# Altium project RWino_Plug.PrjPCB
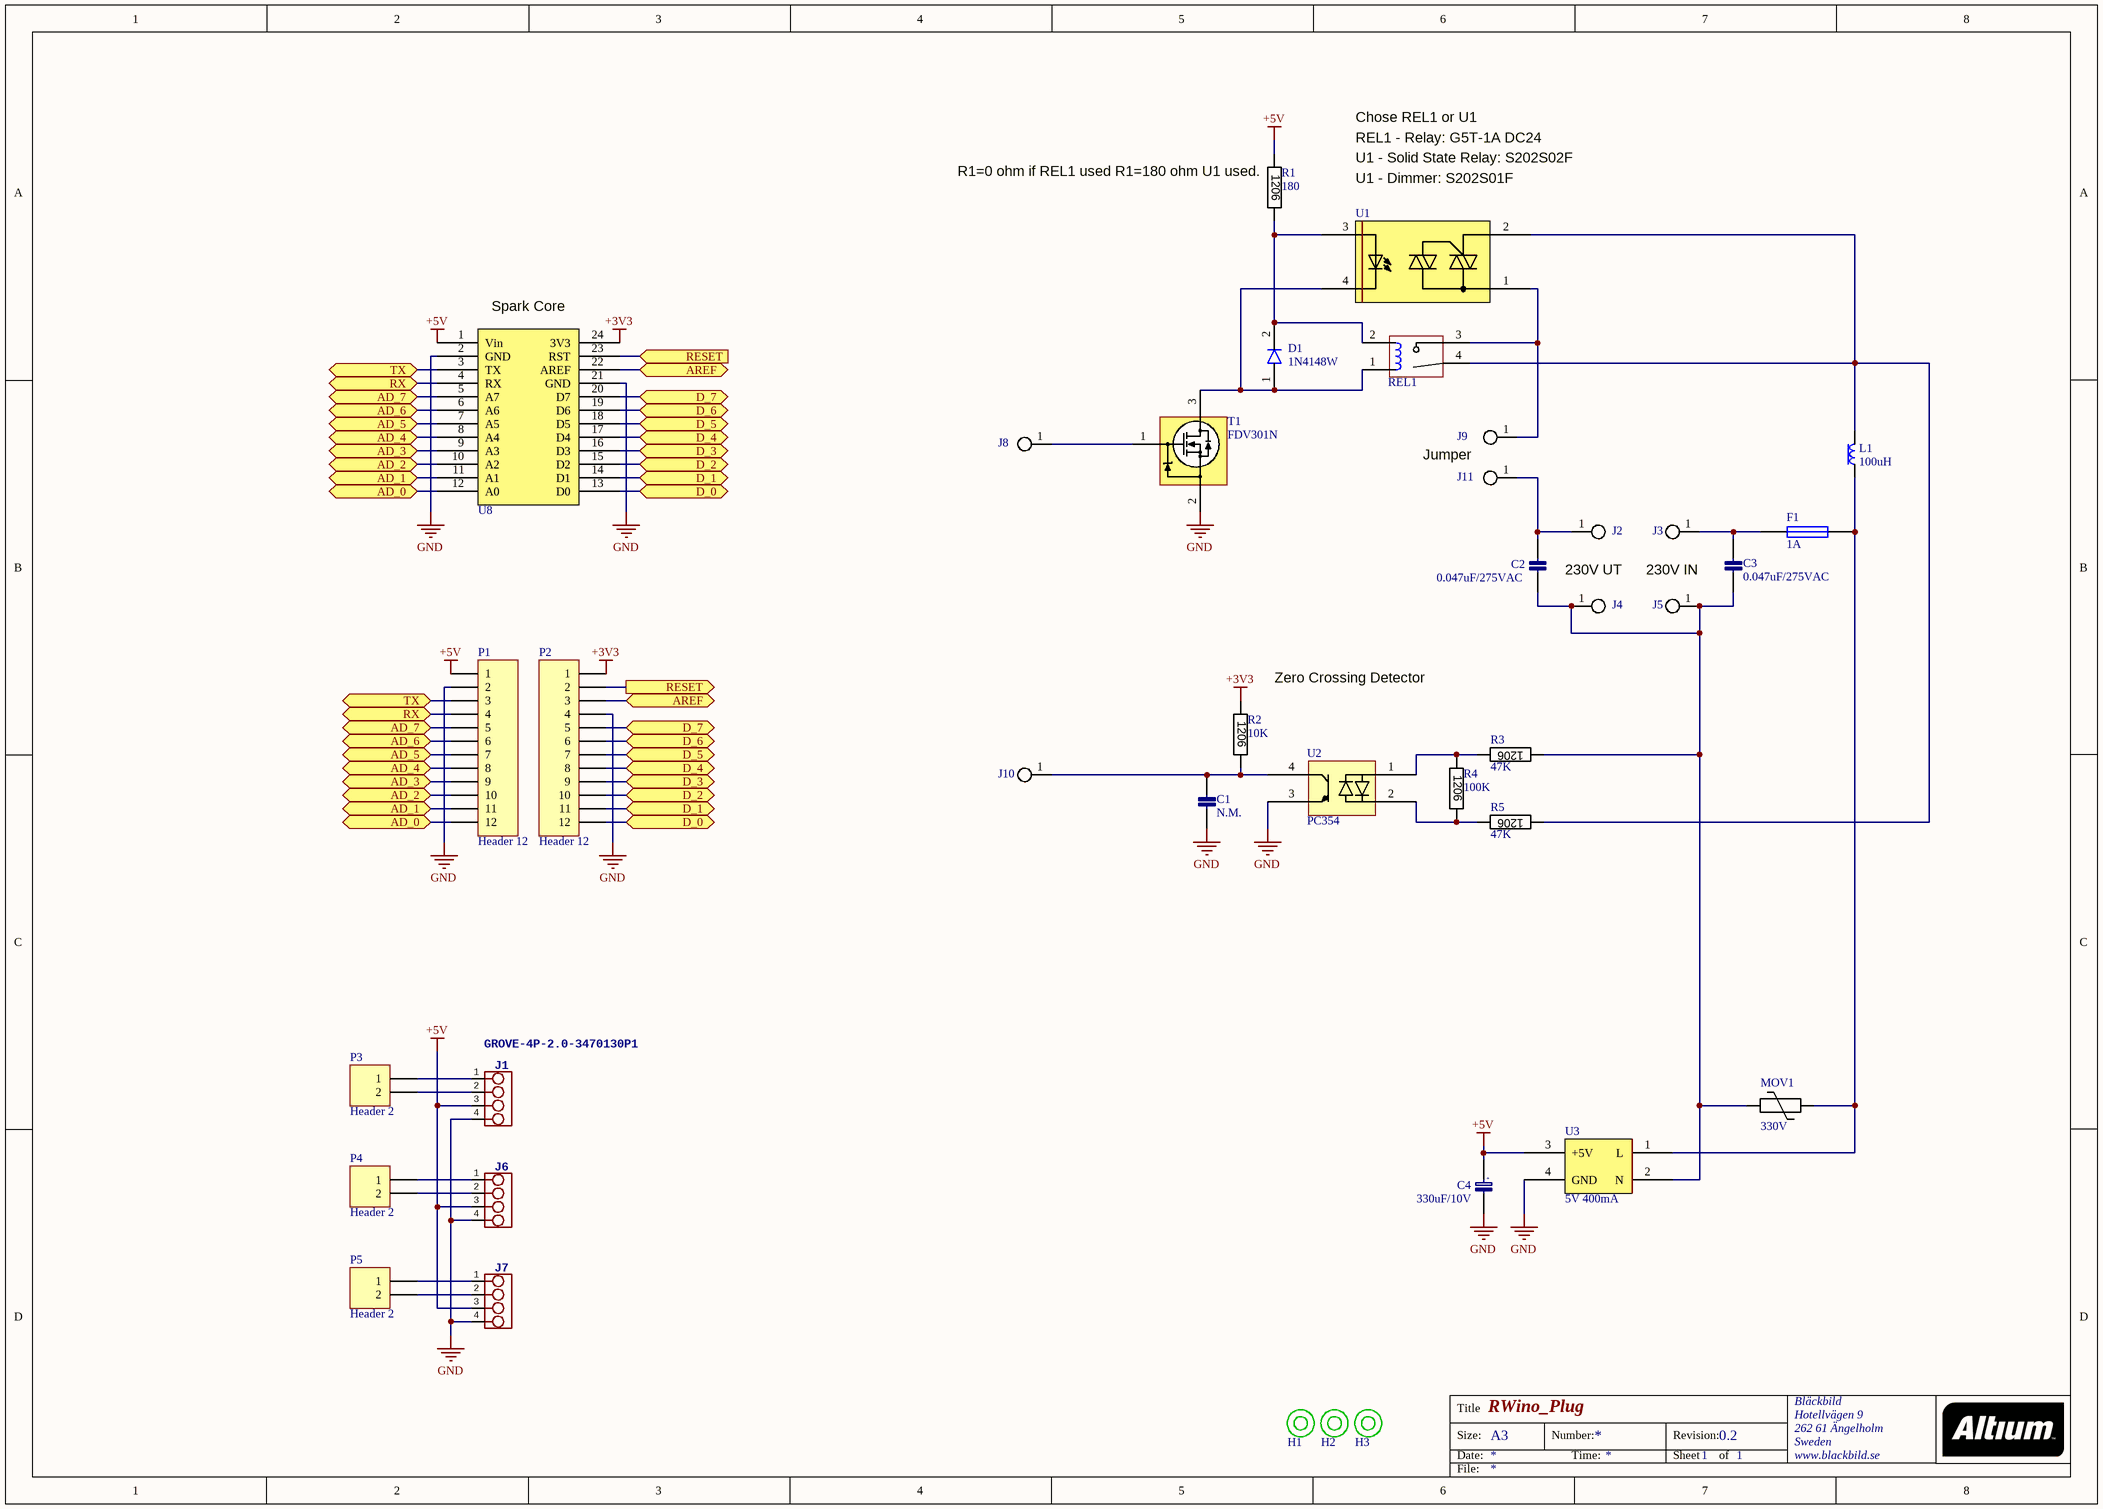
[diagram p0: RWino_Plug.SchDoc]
1 sheet, 38 parts. Net scope: flat (ports and power ports of the same name join across sheets).
Board file: RWino_Plug.PcbDoc

## Sheet RWino_Plug.SchDoc: RWino_Plug
size A3; Organization: Bläckbild; Address1: Hotellvägen 9; Address2: 262 61 Ängelholm; Address3: Sweden; Address4: www.blackbild.se; Revision: 0.2; SheetNumber: 1; SheetTotal: 1

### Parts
C1  value N.M.  [CAPC1206(3216)75_N]  (hidden comment: Ccap)
C2  value 0.047uF/275VAC  [PolyCap_0,047uF/275V]  (hidden comment: 0,047uF/275VAC)
C3  value 0.047uF/275VAC  [PolyCap_0,047uF/275V]  (hidden comment: 0,047uF/275VAC)
C4  value 330uF/10V  [T_Cap_D/7343-31]  (hidden comment: 330uF_Tcap)
D1  1N4148W  [SOD123F]
F1  value 1A  [PIN-W2/E2.8]  (hidden comment: Fuse 1)
H1  Fidus  [Fidus]  (value not drawn)
H2  Fidus  [Fidus]  (value not drawn)
H3  Fidus  [Fidus]  (value not drawn)
J1  GROVE-4P-2.0-3470130P1  [4P-2.0]
J2  Proto_PAD 1.87 mm  [Proto_PAD 1.87 mm]  (value not drawn)
J3  Proto_PAD 1.87 mm  [Proto_PAD 1.87 mm]  (value not drawn)
J4  Proto_PAD 1.87 mm  [Proto_PAD 1.87 mm]  (value not drawn)
J5  Proto_PAD 1.87 mm  [Proto_PAD 1.87 mm]  (value not drawn)
J6  GROVE-4P-2.0-3470130P1  [4P-2.0]  (value not drawn)
J7  GROVE-4P-2.0-3470130P1  [4P-2.0]  (value not drawn)
J8  Proto_PAD 1.87 mm  [Proto_PAD 1.87 mm]  (value not drawn)
J9  Proto_PAD 1.87 mm  [Proto_PAD 1.87 mm]  (value not drawn)
J10  Proto_PAD 1.87 mm  [Proto_PAD 1.87 mm]  (value not drawn)
J11  Proto_PAD 1.87 mm  [Proto_PAD 1.87 mm]  (value not drawn)
L1  100uH  [INDUCTOR 100UH/3A]
MOV1  value 330V  [MOV-14D]  (hidden comment: MOV-14D)
P1  Header 12  [HDR1X12]
P2  Header 12  [HDR1X12]
P3  Header 2  [HDR1X2]
P4  Header 2  [HDR1X2]
P5  Header 2  [HDR1X2]
R1  value 180  [RES1206_33mW]  (hidden comment: R1206)
R2  value 10K  [RES1206_33mW]  (hidden comment: R1206)
R3  value 47K  [RES1206_33mW]  (hidden comment: R1206)
R4  value 100K  [RES1206_33mW]  (hidden comment: R1206)
R5  value 47K  [RES1206_33mW]  (hidden comment: R1206)
REL1  G5T-1A DC24  [G5T-1A]  (value not drawn)
T1  FDV301N  [SOT23]
U1  S202S01F  [S202S01 Series]  (value not drawn)
U2  PC354  [4-SMD]
U3  value 5V 400mA  [RAC02-05SC]  (hidden comment: RAC02-05SC)
U8  Spark Core  [Spark_Core]  (value not drawn)

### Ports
AD_0 (bidir), AD_1 (bidir), AD_2 (bidir), AD_3 (bidir), AD_4 (bidir), AD_5 (bidir), AD_6 (bidir), AD_7 (bidir), AREF (bidir), D_0 (bidir), D_1 (bidir), D_2 (bidir), D_3 (bidir), D_4 (bidir), D_5 (bidir), D_6 (bidir), D_7 (bidir), RESET (in), RESET (out), RX (bidir), TX (bidir)

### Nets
+3V3: P2.1 R2.2 U8.24(3V3)
+5V: C4.1 J1.3 J6.3 J7.3 P1.1 R1.2 U3.3(+5V) U8.1(Vin)
GND: C1.2 C4.2 J1.4 J6.4 J7.4 P1.2 P2.4 T1.2(S) U2.3(E) U3.4(GND) U8.2(GND) U8.21(GND)
NetC1_1: C1.1 J10.1 R2.1 U2.4(C)
NetC2_1: C2.1 J2.1 J11.1
NetC2_2: C2.2 C3.2 J4.1 J5.1 MOV1.2 R3.2 U3.2(N)
NetC3_1: C3.1 F1.2 J3.1
NetD1_1: D1.1(A) REL1.1 T1.3 U1.4
NetD1_2: D1.2(C) R1.1 REL1.2 U1.3
NetF1_1: F1.1 L1.1 MOV1.1 U3.1(L)
NetJ1_1: J1.1 P3.1
NetJ1_2: J1.2 P3.2
NetJ6_1: J6.1 P4.1
NetJ6_2: J6.2 P4.2
NetJ7_1: J7.1 P5.1
NetJ7_2: J7.2 P5.2
NetJ8_1: J8.1 T1.1(G)
NetJ9_1: J9.1 REL1.3 U1.1
NetL1_2: L1.2 R5.2 REL1.4 U1.2
NetP1_3: P1.3 U8.3(TX) ; port TX
NetP1_4: P1.4 U8.4(RX) ; port RX
NetP1_5: P1.5 U8.5(A7) ; port AD_7
NetP1_6: P1.6 U8.6(A6) ; port AD_6
NetP1_7: P1.7 U8.7(A5) ; port AD_5
NetP1_8: P1.8 U8.8(A4) ; port AD_4
NetP1_9: P1.9 U8.9(A3) ; port AD_3
NetP1_10: P1.10 U8.10(A2) ; port AD_2
NetP1_11: P1.11 U8.11(A1) ; port AD_1
NetP1_12: P1.12 U8.12(A0) ; port AD_0
NetP2_2: P2.2 U8.23(RST) ; port RESET
NetP2_3: P2.3 U8.22(AREF) ; port AREF
NetP2_5: P2.5 U8.20(D7) ; port D_7
NetP2_6: P2.6 U8.19(D6) ; port D_6
NetP2_7: P2.7 U8.18(D5) ; port D_5
NetP2_8: P2.8 U8.17(D4) ; port D_4
NetP2_9: P2.9 U8.16(D3) ; port D_3
NetP2_10: P2.10 U8.15(D2) ; port D_2
NetP2_11: P2.11 U8.14(D1) ; port D_1
NetP2_12: P2.12 U8.13(D0) ; port D_0
NetR3_1: R3.1 R4.2 U2.1(A)
NetR4_1: R4.1 R5.1 U2.2(C)

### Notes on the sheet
- (near R1) R1=0 ohm if REL1 used R1=180 ohm U1 used.
- REL1 - Relay: G5T-1A DC24
- U1 - Solid State Relay: S202S02F
- (near U1) U1 - Dimmer: S202S01F
- Chose REL1 or U1
- (near U8) Spark Core
- Jumper
- 230V UT
- 230V IN
- (near R2) Zero Crossing Detector

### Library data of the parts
C1 = Ccap: Multilayer Ceramic Chip Capacitors X7R
C2 C3 = PolyCap_0.047uF/275VAC: Metallized Polypropylene Film EMI Suppression Capacitors 275VAC; Manufactor: Kemet; Manufactor ID: R46KF247050N0K; Suplayer ID: 399-11478-ND
C4 = 330uF_Tcap: Aluminum Electrolytic Type / Surface Mount Type; Manufactor: KEMET; Manufactor ID: T495X337K010ATE035; Suplayer ID: 399-4783-1-ND
D1 = 1N4148W: BAV16W/1N4148W - SURFACE MOUNT FAST SWITCHING DIODE; Manufactor: Fairchild; Manufactor ID: 1N4148WS; Suplayer ID: 1N4148WSFSCT-ND
F1 = Fuse 1: Fuse
J2-J5 J8-J11 = Proto_PAD 1.87 mm: Prototyp Pad 1.87 mm
L1 = Iductor 100uH/3A: Choke Power Inductor  100uH 3A; Manufactor: Talema Group LLC; Manufactor ID: DPO-3.0-100; Suplayer ID: 1295-1171-ND
MOV1 = MOV-14D: MOV-14DxxxK Series - Metal Oxide Varistor; Manufactor: Bourns; Manufactor ID: MOV-14D361K; Suplayer ID: MOV-14D361K-ND
P1 P2 = Header 12: Header, 12-Pin
P3-P5 = Header 2: Header, 2-Pin
R1 = R1206: Anti-Surge Thick Film Chip Resistors; Manufactor: Vishay; Manufactor ID: CRCW1206180RFKEA; Suplayer ID: 541-180FCT-ND
R2 = R1206: Anti-Surge Thick Film Chip Resistors; Manufactor: Vishay Dale; Manufactor ID: CRCW120610K0JNEA; Suplayer ID: 541-10KECT-ND
R3 R5 = R1206: Anti-Surge Thick Film Chip Resistors; Manufactor: ROHM; Manufactor ID: KTR18EZPF4702; Suplayer ID: RHM47KAICT-ND
R4 = R1206: Anti-Surge Thick Film Chip Resistors; Manufactor: ROHM; Manufactor ID: KTR18EZPF1003; Suplayer ID: RHM100KAICT-ND
REL1 = G5T-1A DC24: Slim Relay capable of switching up to 5 A; Manufactor: Omron; Suplayer ID: Z2776-ND
T1 = FDV301N: Digital FET, N-Channel; Manufactor: FAIRCHILD; Suplayer ID: FDV301NCT-ND
U1 = S202S01F: RELAY SSR 240VAC 8A TRIAC 4-SIP; Manufactor: Sharp; Suplayer ID: 425-2402-5-ND
U2 = PC354NJ0000F: SMD 4pin AC Photocoupler; Manufactor: Sharp; Suplayer ID: 425-2088-1-ND
U3 = RAC02-05SC: AC/DC-Converter 100-240 Vac / 5V 400mA; Manufactor: Recom Power; Suplayer ID: 945-1401-5-ND
U8 = Spark Core: Spark Core WiFi MPU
